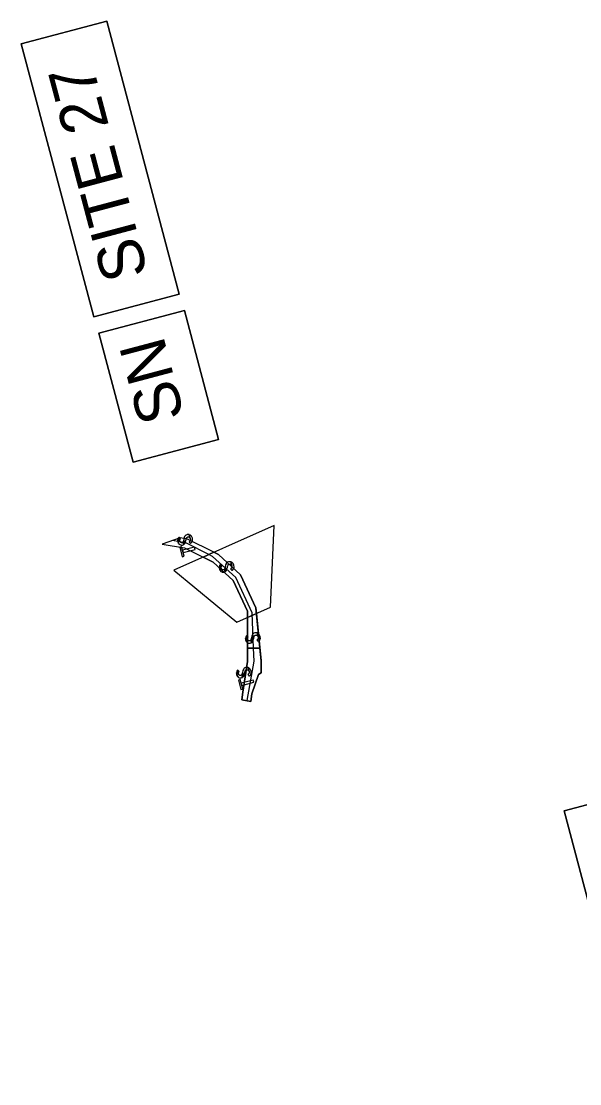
# Model space of a CAD drawing. Extents: x 474218 to 481634, y 484357 to 504997.
# Drawn here: x 474322.1 to 474505.5, y 503544.9 to 503893.5 of the extents above; entities that cross this region are included whole.
import ezdxf

# ---------------------------------------------------------------- set-up
doc = ezdxf.new("R2010")
doc.units = 0
for name, color, linetype in [('Exist Hydro Jurisdictional Stream or Body of Water', 7, 'Continuous'), ('Old_Level_29', 7, 'Continuous'), ('Prop Earthen Structure Impacts In Surface Waters Hatching CELL', 7, 'Continuous'), ('Prop Grid Mask', 7, 'Continuous'), ('Scratch_Level_4', 7, 'Continuous'), ('Temp Earthen Structure Impacts In Surface Waters Hatching CELL', 7, 'Continuous')]:
    doc.layers.add(name, color=color, linetype=linetype)

msp = doc.modelspace()

# ---------------------------------------------------------------- linework, layer by layer
at = {"layer": 'Exist Hydro Jurisdictional Stream or Body of Water'}
msp.add_lwpolyline([(474358.84, 503748.87), (474347.61, 503791.13), (474375.72, 503798.6), (474386.95, 503756.34)], close=True, dxfattribs=at)
at = {"layer": 'Old_Level_29'}
for points in [[(474345.91, 503796.52), (474322.12, 503886.07), (474350.24, 503893.53), (474374.03, 503803.99)], [(474524.22, 503544.88), (474500.44, 503634.43), (474528.55, 503641.89), (474552.34, 503552.35)]]:
    msp.add_lwpolyline(points, close=True, dxfattribs=at)
at = {"layer": 'Prop Earthen Structure Impacts In Surface Waters Hatching CELL'}
msp.add_line((474396.4, 503687.76), (474400.48, 503687.86), dxfattribs=at)
msp.add_lwpolyline([(474400.48, 503687.86), (474399.17, 503701.09), (474394.13, 503711.84), (474386.86, 503718.56), (474385.39, 503719.29), (474381.83, 503717.71), (474385.14, 503716.06), (474391.67, 503710.04), (474396.39, 503699.95), (474396.4, 503687.76)], dxfattribs=at)
for points in [[(474388.92, 503712.84), (474389.08, 503712.9), (474388.85, 503713.75), (474388.71, 503713.61), (474388.46, 503713.53), (474388.45, 503713.52), (474388.38, 503713.53), (474388.2, 503713.55), (474388.13, 503713.6), (474388.03, 503713.67), (474387.98, 503713.7), (474387.96, 503713.73), (474387.91, 503713.84), (474387.83, 503713.98), (474387.49, 503715.23), (474387.43, 503715.17), (474387.26, 503714.91), (474387.21, 503714.85), (474387.12, 503714.41), (474387.42, 503713.29), (474387.7, 503713.01), (474387.78, 503712.93), (474388.05, 503712.82), (474388.14, 503712.79), (474388.19, 503712.77), (474388.22, 503712.75), (474388.23, 503712.75), (474388.27, 503712.75), (474388.35, 503712.75), (474388.41, 503712.75), (474388.59, 503712.75), (474388.65, 503712.75), (474388.67, 503712.75)], [(474387.4, 503713.34), (474387.42, 503713.29), (474387.12, 503714.41), (474387.12, 503714.39), (474387.19, 503713.81), (474387.19, 503713.81)], [(474387.91, 503714.64), (474388.04, 503714.82), (474387.79, 503715.09), (474387.71, 503715.19), (474387.59, 503715.31), (474387.56, 503715.29), (474387.55, 503715.28), (474387.53, 503715.26), (474387.49, 503715.23), (474387.83, 503713.97), (474387.78, 503714.3), (474387.8, 503714.36), (474387.8, 503714.38), (474387.82, 503714.44), (474387.87, 503714.58)], [(474389.32, 503713.1), (474389.4, 503713.17), (474389.08, 503714.38), (474389.04, 503714.14), (474388.92, 503713.82), (474388.85, 503713.75), (474389.08, 503712.9), (474389.15, 503712.95)], [(474391.14, 503715.14), (474391.27, 503714.87), (474390.93, 503716.13), (474390.87, 503716.15), (474390.87, 503716.15), (474390.86, 503716.16), (474390.75, 503716.19), (474390.71, 503716.19), (474390.68, 503716.19), (474390.54, 503716.18), (474390.48, 503716.18), (474390.43, 503716.18), (474390.25, 503716.17), (474390.15, 503716.13), (474389.9, 503716.03), (474389.79, 503715.99), (474389.72, 503715.92), (474389.57, 503715.77), (474389.57, 503715.77), (474389.45, 503715.66), (474389.39, 503715.52), (474389.25, 503715.18), (474389.22, 503715.08), (474389.12, 503714.62), (474389.08, 503714.38), (474389.4, 503713.17), (474389.47, 503713.29), (474389.63, 503713.55), (474389.66, 503713.65), (474389.78, 503714.08), (474389.82, 503714.28), (474389.88, 503714.6), (474389.96, 503714.98), (474390.03, 503715.09), (474390.11, 503715.23), (474390.35, 503715.38), (474390.45, 503715.4), (474390.63, 503715.43), (474390.68, 503715.41), (474390.75, 503715.4), (474390.9, 503715.37), (474390.94, 503715.33), (474390.99, 503715.29), (474391.12, 503715.17), (474391.13, 503715.16)], [(474392.02, 503714.37), (474391.95, 503715.01), (474391.68, 503715.63), (474391.68, 503715.63), (474391.28, 503715.99), (474391.23, 503716.03), (474390.93, 503716.13), (474391.27, 503714.87), (474391.31, 503714.51), (474391.31, 503714.51), (474391.3, 503714.48), (474391.26, 503714.28), (474391.24, 503714.21), (474391.22, 503714.18), (474391.11, 503714.03), (474391.07, 503713.97), (474391.03, 503713.94), (474390.88, 503713.83), (474391.14, 503713.51), (474391.21, 503713.42), (474391.3, 503713.31), (474391.43, 503713.39), (474391.45, 503713.41), (474391.48, 503713.43), (474391.57, 503713.48), (474391.58, 503713.5), (474391.58, 503713.5), (474391.62, 503713.55), (474391.83, 503713.8), (474391.85, 503713.83), (474392.02, 503714.36)], [(474396.03, 503690.01), (474396.05, 503689.96), (474395.76, 503691.08), (474395.75, 503691.06), (474395.82, 503690.48), (474395.82, 503690.48)], [(474397.55, 503689.51), (474397.71, 503689.57), (474397.49, 503690.43), (474397.35, 503690.28), (474397.1, 503690.2), (474397.08, 503690.19), (474397.02, 503690.2), (474396.84, 503690.22), (474396.76, 503690.27), (474396.66, 503690.34), (474396.62, 503690.37), (474396.6, 503690.4), (474396.54, 503690.51), (474396.46, 503690.65), (474396.13, 503691.9), (474396.06, 503691.85), (474395.89, 503691.58), (474395.85, 503691.52), (474395.76, 503691.08), (474396.05, 503689.96), (474396.34, 503689.68), (474396.42, 503689.6), (474396.69, 503689.5), (474396.78, 503689.46), (474396.82, 503689.44), (474396.86, 503689.43), (474396.87, 503689.43), (474396.91, 503689.43), (474396.99, 503689.43), (474397.05, 503689.43), (474397.22, 503689.43), (474397.29, 503689.43), (474397.3, 503689.43)], [(474396.55, 503691.32), (474396.67, 503691.49), (474396.43, 503691.77), (474396.34, 503691.86), (474396.23, 503691.99), (474396.2, 503691.96), (474396.19, 503691.95), (474396.16, 503691.93), (474396.13, 503691.9), (474396.46, 503690.65), (474396.42, 503690.98), (474396.43, 503691.03), (474396.44, 503691.05), (474396.46, 503691.11), (474396.5, 503691.26)], [(474397.95, 503689.77), (474398.04, 503689.84), (474397.72, 503691.05), (474397.68, 503690.81), (474397.55, 503690.49), (474397.49, 503690.43), (474397.72, 503689.57), (474397.78, 503689.62)], [(474399.78, 503691.81), (474399.9, 503691.54), (474399.56, 503692.81), (474399.51, 503692.82), (474399.5, 503692.83), (474399.49, 503692.83), (474399.38, 503692.87), (474399.35, 503692.86), (474399.32, 503692.86), (474399.18, 503692.85), (474399.12, 503692.85), (474399.07, 503692.85), (474398.89, 503692.84), (474398.78, 503692.8), (474398.53, 503692.71), (474398.43, 503692.66), (474398.35, 503692.59), (474398.2, 503692.45), (474398.2, 503692.44), (474398.09, 503692.33), (474398.03, 503692.19), (474397.88, 503691.86), (474397.86, 503691.75), (474397.76, 503691.29), (474397.72, 503691.05), (474398.04, 503689.84), (474398.11, 503689.96), (474398.26, 503690.23), (474398.29, 503690.32), (474398.41, 503690.75), (474398.45, 503690.96), (474398.51, 503691.27), (474398.6, 503691.65), (474398.66, 503691.77), (474398.75, 503691.9), (474398.98, 503692.06), (474399.09, 503692.07), (474399.27, 503692.1), (474399.32, 503692.09), (474399.38, 503692.07), (474399.54, 503692.04), (474399.57, 503692), (474399.62, 503691.96), (474399.75, 503691.84), (474399.77, 503691.83)], [(474400.65, 503691.04), (474400.58, 503691.69), (474400.31, 503692.3), (474400.31, 503692.3), (474399.92, 503692.66), (474399.87, 503692.71), (474399.56, 503692.81), (474399.9, 503691.54), (474399.94, 503691.19), (474399.94, 503691.18), (474399.94, 503691.15), (474399.89, 503690.96), (474399.87, 503690.88), (474399.85, 503690.85), (474399.75, 503690.7), (474399.7, 503690.64), (474399.66, 503690.61), (474399.51, 503690.5), (474399.78, 503690.18), (474399.85, 503690.09), (474399.94, 503689.99), (474400.06, 503690.07), (474400.09, 503690.08), (474400.12, 503690.1), (474400.2, 503690.16), (474400.21, 503690.17), (474400.21, 503690.17), (474400.25, 503690.22), (474400.46, 503690.47), (474400.49, 503690.5), (474400.65, 503691.03)]]:
    msp.add_lwpolyline(points, close=True, dxfattribs=at)
at = {"layer": 'Prop Grid Mask'}
for points in [[(474374.03, 503803.99), (474350.24, 503893.53), (474322.12, 503886.07), (474345.91, 503796.52)], [(474386.95, 503756.34), (474375.72, 503798.6), (474347.61, 503791.13), (474358.84, 503748.87)], [(474552.34, 503552.35), (474528.55, 503641.89), (474500.44, 503634.43), (474524.22, 503544.88)]]:
    msp.add_lwpolyline(points, close=True, dxfattribs=at)
at = {"layer": 'Scratch_Level_4'}
for points in [[(474392.97, 503696.39), (474403.93, 503701.26), (474405.16, 503728.07), (474372.26, 503713.46)], [(474381.83, 503717.71), (474385.39, 503719.29), (474376.72, 503723.6), (474374.34, 503723.99), (474368.4, 503721.94), (474375.78, 503720.72)], [(474381.83, 503717.71), (474385.39, 503719.29), (474376.72, 503723.6), (474374.34, 503723.99), (474368.4, 503721.94), (474375.78, 503720.72)], [(474396.39, 503697.92), (474399.36, 503699.23), (474399.17, 503701.09), (474394.13, 503711.84), (474386.86, 503718.56), (474385.39, 503719.29), (474381.83, 503717.71), (474385.14, 503716.06), (474391.67, 503710.04), (474396.39, 503699.95)], [(474396.39, 503697.92), (474399.36, 503699.23), (474399.17, 503701.09), (474394.13, 503711.84), (474386.86, 503718.56), (474385.39, 503719.29), (474381.83, 503717.71), (474385.14, 503716.06), (474391.67, 503710.04), (474396.39, 503699.95)], [(474396.39, 503697.92), (474396.39, 503699.95), (474391.67, 503710.04), (474385.14, 503716.06), (474381.83, 503717.71), (474385.39, 503719.29), (474386.86, 503718.56), (474394.13, 503711.84), (474399.17, 503701.09), (474399.36, 503699.23)], [(474396.39, 503697.92), (474396.39, 503699.95), (474391.67, 503710.04), (474385.14, 503716.06), (474381.83, 503717.71), (474385.39, 503719.29), (474386.86, 503718.56), (474394.13, 503711.84), (474399.17, 503701.09), (474399.36, 503699.23)], [(474394.61, 503670.88), (474394.85, 503673.39), (474396.4, 503683.43), (474396.39, 503697.92), (474399.36, 503699.23), (474400.88, 503683.71), (474400.86, 503679.71), (474400.03, 503679.18), (474397.81, 503672.78), (474397.57, 503670.34)], [(474394.61, 503670.88), (474394.85, 503673.39), (474396.4, 503683.43), (474396.39, 503697.92), (474399.36, 503699.23), (474400.88, 503683.71), (474400.86, 503679.71), (474400.03, 503679.18), (474397.81, 503672.78), (474397.57, 503670.34)]]:
    msp.add_lwpolyline(points, close=True, dxfattribs=at)
for points in [[(474383.71, 503718.58), (474376.37, 503722.24), (474371.79, 503723.11)], [(474398.43, 503687.83), (474397.94, 503699.37), (474392.61, 503711.05), (474384.93, 503717.92), (474383.71, 503718.58)], [(474396.29, 503670.64), (474398.57, 503683.59), (474398.43, 503687.83)]]:
    msp.add_lwpolyline(points, dxfattribs=at)
at = {"layer": 'Temp Earthen Structure Impacts In Surface Waters Hatching CELL'}
msp.add_line((474400.48, 503687.86), (474396.4, 503687.76), dxfattribs=at)
for points in [[(474377.53, 503724.04), (474377.65, 503723.77), (474377.32, 503725.03), (474377.26, 503725.05), (474377.26, 503725.05), (474377.24, 503725.06), (474377.13, 503725.09), (474377.1, 503725.09), (474377.07, 503725.09), (474376.93, 503725.08), (474376.87, 503725.08), (474376.82, 503725.08), (474376.64, 503725.07), (474376.53, 503725.03), (474376.29, 503724.93), (474376.18, 503724.89), (474376.1, 503724.82), (474375.95, 503724.67), (474375.95, 503724.67), (474375.84, 503724.56), (474375.78, 503724.42), (474375.63, 503724.08), (474375.61, 503723.98), (474375.51, 503723.52), (474375.47, 503723.28), (474375.79, 503722.07), (474375.86, 503722.19), (474376.01, 503722.45), (474376.04, 503722.55), (474376.16, 503722.98), (474376.2, 503723.18), (474376.27, 503723.5), (474376.35, 503723.88), (474376.42, 503723.99), (474376.5, 503724.13), (474376.73, 503724.28), (474376.84, 503724.3), (474377.02, 503724.33), (474377.07, 503724.31), (474377.14, 503724.3), (474377.29, 503724.27), (474377.33, 503724.23), (474377.38, 503724.19), (474377.5, 503724.07), (474377.52, 503724.06)], [(474378.4, 503723.27), (474378.33, 503723.91), (474378.07, 503724.53), (474378.06, 503724.53), (474377.67, 503724.89), (474377.62, 503724.93), (474377.32, 503725.03), (474377.65, 503723.77), (474377.69, 503723.41), (474377.69, 503723.41), (474377.69, 503723.38), (474377.64, 503723.18), (474377.62, 503723.11), (474377.6, 503723.08), (474377.5, 503722.93), (474377.45, 503722.87), (474377.41, 503722.84), (474377.26, 503722.73), (474377.53, 503722.41), (474377.6, 503722.32), (474377.69, 503722.21), (474377.81, 503722.29), (474377.84, 503722.31), (474377.87, 503722.33), (474377.95, 503722.38), (474377.96, 503722.4), (474377.96, 503722.4), (474378, 503722.45), (474378.21, 503722.7), (474378.24, 503722.73), (474378.4, 503723.26)], [(474373.78, 503722.24), (474373.81, 503722.19), (474373.51, 503723.31), (474373.5, 503723.29), (474373.57, 503722.71), (474373.57, 503722.71)], [(474375.3, 503721.74), (474375.47, 503721.8), (474375.24, 503722.65), (474375.1, 503722.51), (474374.85, 503722.43), (474374.83, 503722.42), (474374.77, 503722.43), (474374.59, 503722.45), (474374.51, 503722.5), (474374.41, 503722.57), (474374.37, 503722.6), (474374.35, 503722.63), (474374.29, 503722.74), (474374.21, 503722.88), (474373.88, 503724.13), (474373.81, 503724.07), (474373.64, 503723.81), (474373.6, 503723.75), (474373.51, 503723.31), (474373.81, 503722.19), (474374.09, 503721.91), (474374.17, 503721.83), (474374.44, 503721.72), (474374.53, 503721.69), (474374.58, 503721.67), (474374.61, 503721.65), (474374.62, 503721.65), (474374.66, 503721.65), (474374.74, 503721.65), (474374.8, 503721.65), (474374.97, 503721.65), (474375.04, 503721.65), (474375.06, 503721.65)], [(474374.3, 503723.54), (474374.43, 503723.72), (474374.18, 503723.99), (474374.09, 503724.09), (474373.98, 503724.21), (474373.95, 503724.19), (474373.94, 503724.18), (474373.91, 503724.16), (474373.88, 503724.13), (474374.21, 503722.87), (474374.17, 503723.2), (474374.18, 503723.26), (474374.19, 503723.28), (474374.21, 503723.34), (474374.25, 503723.48)], [(474375.7, 503722), (474375.79, 503722.07), (474375.47, 503723.28), (474375.43, 503723.04), (474375.3, 503722.72), (474375.24, 503722.65), (474375.47, 503721.8), (474375.53, 503721.85)], [(474374.98, 503717.81), (474375.62, 503717.98), (474374.78, 503721.12), (474374.15, 503720.95)], [(474375.3, 503719.18), (474379.19, 503720.22), (474379, 503720.95), (474375.1, 503719.92)], [(474394.59, 503678.15), (474394.75, 503678.21), (474394.52, 503679.06), (474394.38, 503678.92), (474394.13, 503678.84), (474394.12, 503678.83), (474394.05, 503678.84), (474393.87, 503678.86), (474393.8, 503678.91), (474393.7, 503678.98), (474393.65, 503679.01), (474393.63, 503679.04), (474393.57, 503679.15), (474393.5, 503679.29), (474393.16, 503680.54), (474393.09, 503680.48), (474392.92, 503680.22), (474392.88, 503680.16), (474392.79, 503679.72), (474393.09, 503678.6), (474393.37, 503678.32), (474393.45, 503678.24), (474393.72, 503678.13), (474393.81, 503678.1), (474393.86, 503678.08), (474393.89, 503678.06), (474393.9, 503678.06), (474393.94, 503678.06), (474394.02, 503678.06), (474394.08, 503678.06), (474394.26, 503678.06), (474394.32, 503678.06), (474394.34, 503678.06)], [(474393.06, 503678.65), (474393.09, 503678.6), (474392.79, 503679.72), (474392.79, 503679.7), (474392.86, 503679.12), (474392.86, 503679.12)], [(474393.58, 503679.95), (474393.71, 503680.13), (474393.46, 503680.4), (474393.38, 503680.5), (474393.26, 503680.62), (474393.23, 503680.6), (474393.22, 503680.59), (474393.2, 503680.57), (474393.16, 503680.54), (474393.5, 503679.29), (474393.45, 503679.61), (474393.47, 503679.67), (474393.47, 503679.69), (474393.49, 503679.75), (474393.54, 503679.89)], [(474394.99, 503678.41), (474395.07, 503678.48), (474394.75, 503679.69), (474394.71, 503679.45), (474394.59, 503679.13), (474394.52, 503679.06), (474394.75, 503678.21), (474394.82, 503678.26)], [(474396.81, 503680.45), (474396.93, 503680.18), (474396.6, 503681.44), (474396.54, 503681.46), (474396.54, 503681.46), (474396.52, 503681.47), (474396.42, 503681.5), (474396.38, 503681.5), (474396.35, 503681.5), (474396.21, 503681.49), (474396.15, 503681.49), (474396.1, 503681.49), (474395.92, 503681.48), (474395.82, 503681.44), (474395.57, 503681.34), (474395.46, 503681.3), (474395.38, 503681.23), (474395.24, 503681.08), (474395.24, 503681.08), (474395.12, 503680.97), (474395.06, 503680.83), (474394.92, 503680.49), (474394.89, 503680.39), (474394.79, 503679.93), (474394.75, 503679.69), (474395.07, 503678.48), (474395.14, 503678.6), (474395.3, 503678.86), (474395.32, 503678.96), (474395.45, 503679.39), (474395.49, 503679.6), (474395.55, 503679.91), (474395.63, 503680.29), (474395.7, 503680.4), (474395.78, 503680.54), (474396.01, 503680.69), (474396.12, 503680.71), (474396.3, 503680.74), (474396.35, 503680.72), (474396.42, 503680.71), (474396.57, 503680.68), (474396.61, 503680.64), (474396.66, 503680.6), (474396.79, 503680.48), (474396.8, 503680.47)], [(474397.68, 503679.68), (474397.62, 503680.32), (474397.35, 503680.94), (474397.35, 503680.94), (474396.95, 503681.3), (474396.9, 503681.34), (474396.6, 503681.44), (474396.93, 503680.18), (474396.98, 503679.82), (474396.98, 503679.82), (474396.97, 503679.79), (474396.92, 503679.59), (474396.91, 503679.52), (474396.89, 503679.49), (474396.78, 503679.34), (474396.74, 503679.28), (474396.7, 503679.25), (474396.55, 503679.14), (474396.81, 503678.82), (474396.88, 503678.73), (474396.97, 503678.62), (474397.09, 503678.7), (474397.12, 503678.72), (474397.15, 503678.74), (474397.23, 503678.79), (474397.24, 503678.81), (474397.25, 503678.81), (474397.29, 503678.86), (474397.5, 503679.11), (474397.52, 503679.14), (474397.68, 503679.67)], [(474394.27, 503674.22), (474394.9, 503674.39), (474394.07, 503677.53), (474393.43, 503677.36)], [(474394.58, 503675.59), (474398.47, 503676.63), (474398.28, 503677.36), (474394.38, 503676.33)]]:
    msp.add_lwpolyline(points, close=True, dxfattribs=at)
for points in [[(474381.83, 503717.71), (474385.39, 503719.29), (474376.72, 503723.6), (474374.34, 503723.99), (474368.4, 503721.94), (474375.78, 503720.72), (474381.83, 503717.71)], [(474396.4, 503687.76), (474396.4, 503683.43), (474394.85, 503673.39), (474394.61, 503670.88), (474397.57, 503670.34)], [(474397.57, 503670.34), (474397.81, 503672.78), (474400.03, 503679.18), (474400.86, 503679.71), (474400.88, 503683.71), (474400.48, 503687.86)]]:
    msp.add_lwpolyline(points, dxfattribs=at)

# ---------------------------------------------------------------- texts
at = {"layer": 'Exist Hydro Jurisdictional Stream or Body of Water'}
msp.add_text('SN', height=15, rotation=104.8782, dxfattribs=at).set_placement((474375.79, 503763.86))
at = {"layer": 'Old_Level_29'}
msp.add_text('SITE 27', height=15, rotation=104.8782, dxfattribs=at).set_placement((474363.89, 503810.64))

doc.saveas('drawing.dxf')
